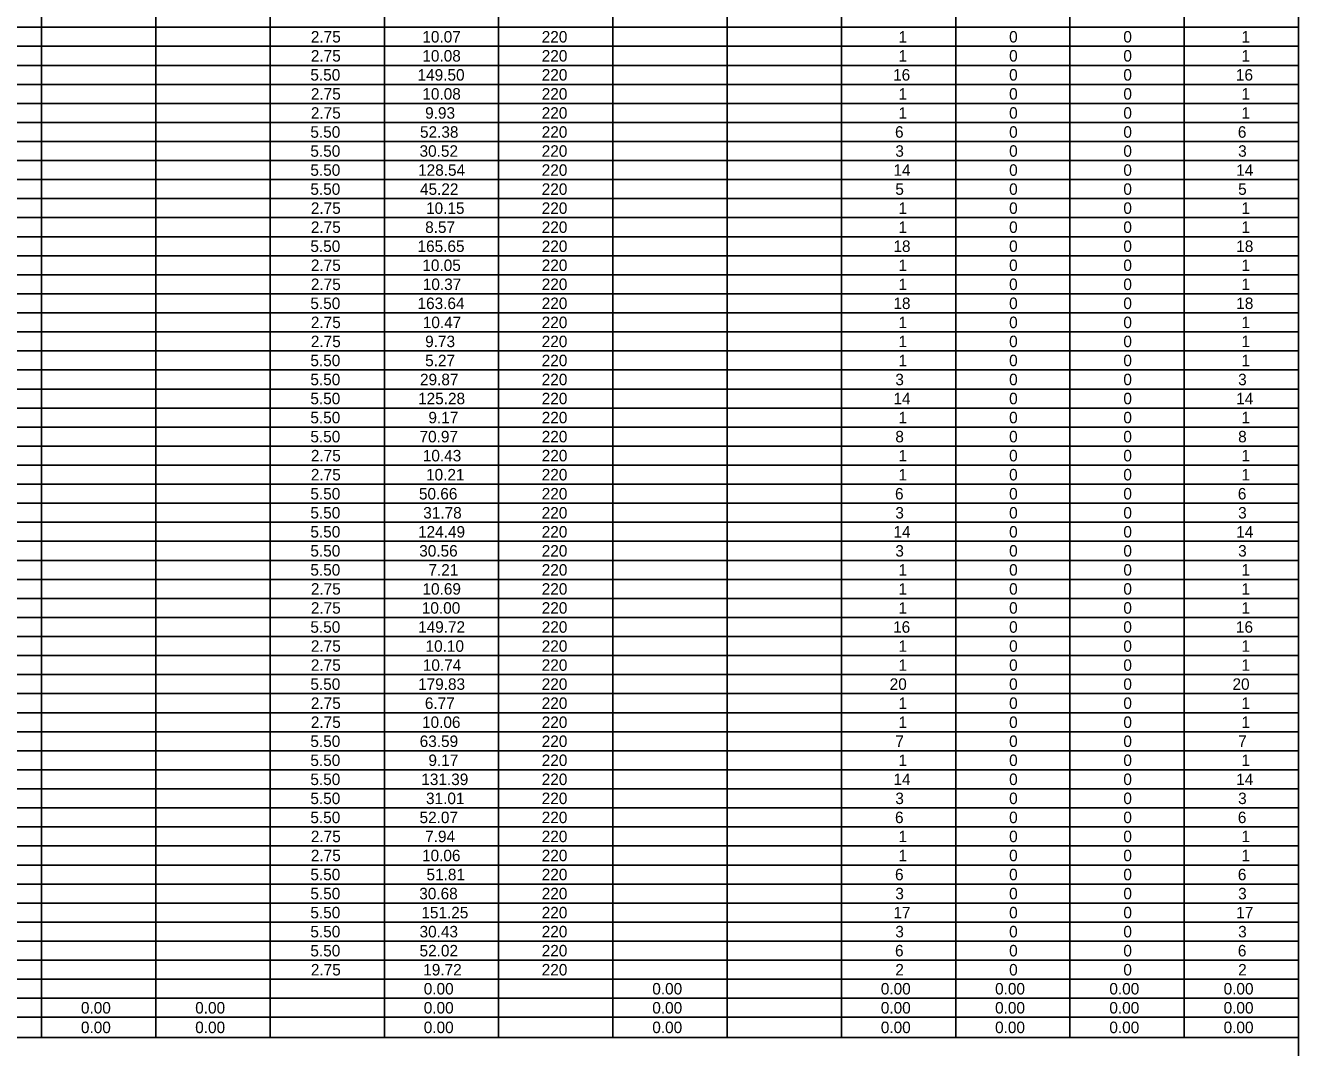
# Model space of a CAD drawing. Extents: x 1226590 to 1228573, y 151304 to 154224.
# Drawn here: x 1228019 to 1228573, y 153319 to 153764 of the extents above; entities that cross this region are included whole.
import ezdxf

# ---------------------------------------------------------------- set-up
doc = ezdxf.new("R2010")
doc.units = 0
doc.layers.add('R_Dimension', color=7, linetype='Continuous')

msp = doc.modelspace()

# ---------------------------------------------------------------- linework, layer by layer
at = {"layer": 'R_Dimension'}
for p, q in [((1228572.93, 152627.62), (1228572.93, 154214.43)), ((1228025.96, 153323.28), (1228025.96, 153928.75)), ((1228075.68, 153323.28), (1228075.68, 153928.75)), ((1228125.41, 153323.28), (1228125.41, 153928.75)), ((1228175.13, 153323.28), (1228175.13, 153928.75)), ((1228224.86, 153323.28), (1228224.86, 153928.75)), ((1228274.58, 153323.28), (1228274.58, 153928.75)), ((1228324.31, 153323.28), (1228324.31, 153928.75)), ((1228374.03, 153323.28), (1228374.03, 153928.75)), ((1228423.76, 153323.28), (1228423.76, 153928.75)), ((1228473.48, 153323.28), (1228473.48, 153928.75)), ((1228523.21, 153323.28), (1228523.21, 153928.75)), ((1226590.27, 153763), (1228572.93, 153763)), ((1226590.27, 153754.72), (1228572.93, 153754.72)), ((1226590.27, 153746.43), (1228572.93, 153746.43)), ((1226590.27, 153738.14), (1228572.93, 153738.14)), ((1226590.27, 153729.85), (1228572.93, 153729.85)), ((1226590.27, 153721.57), (1228572.93, 153721.57)), ((1226590.27, 153713.28), (1228572.93, 153713.28)), ((1226590.27, 153704.99), (1228572.93, 153704.99)), ((1226590.27, 153696.7), (1228572.93, 153696.7)), ((1226590.27, 153688.42), (1228572.93, 153688.42)), ((1226590.27, 153680.13), (1228572.93, 153680.13)), ((1226590.27, 153671.84), (1228572.93, 153671.84)), ((1226590.27, 153663.55), (1228572.93, 153663.55)), ((1226590.27, 153655.27), (1228572.93, 153655.27)), ((1226590.27, 153646.98), (1228572.93, 153646.98)), ((1226590.27, 153638.69), (1228572.93, 153638.69)), ((1226590.27, 153630.4), (1228572.93, 153630.4)), ((1226590.27, 153622.12), (1228572.93, 153622.12)), ((1226590.27, 153613.83), (1228572.93, 153613.83)), ((1226590.27, 153605.54), (1228572.93, 153605.54)), ((1226590.27, 153597.25), (1228572.93, 153597.25)), ((1226590.27, 153588.97), (1228572.93, 153588.97)), ((1226590.27, 153580.68), (1228572.93, 153580.68)), ((1226590.27, 153572.39), (1228572.93, 153572.39)), ((1226590.27, 153564.1), (1228572.93, 153564.1)), ((1226590.27, 153555.82), (1228572.93, 153555.82)), ((1226590.27, 153547.53), (1228572.93, 153547.53)), ((1226590.27, 153539.24), (1228572.93, 153539.24)), ((1226590.27, 153530.95), (1228572.93, 153530.95)), ((1226590.27, 153522.67), (1228572.93, 153522.67)), ((1226590.27, 153514.38), (1228572.93, 153514.38)), ((1226590.27, 153506.09), (1228572.93, 153506.09)), ((1226590.27, 153497.8), (1228572.93, 153497.8)), ((1226590.27, 153489.52), (1228572.93, 153489.52)), ((1226590.27, 153481.23), (1228572.93, 153481.23)), ((1226590.27, 153472.94), (1228572.93, 153472.94)), ((1226590.27, 153464.65), (1228572.93, 153464.65)), ((1226590.27, 153456.37), (1228572.93, 153456.37)), ((1226590.27, 153448.08), (1228572.93, 153448.08)), ((1226590.27, 153439.79), (1228572.93, 153439.79)), ((1226590.27, 153431.5), (1228572.93, 153431.5)), ((1226590.27, 153423.22), (1228572.93, 153423.22)), ((1226590.27, 153414.93), (1228572.93, 153414.93)), ((1226590.27, 153406.64), (1228572.93, 153406.64)), ((1226590.27, 153398.35), (1228572.93, 153398.35)), ((1226590.27, 153390.07), (1228572.93, 153390.07)), ((1226590.27, 153381.78), (1228572.93, 153381.78)), ((1226590.27, 153373.49), (1228572.93, 153373.49)), ((1226590.27, 153365.2), (1228572.93, 153365.2)), ((1226590.27, 153356.92), (1228572.93, 153356.92)), ((1226590.27, 153348.63), (1228572.93, 153348.63)), ((1226590.27, 153340.34), (1228572.93, 153340.34)), ((1226590.27, 153332.05), (1228572.93, 153332.05)), ((1226590.27, 153323.28), (1228572.93, 153323.28))]:
    msp.add_line(p, q, dxfattribs=at)

# ---------------------------------------------------------------- texts
for s, p in [('2.75', (1228143.14, 153756.36)), ('10.07', (1228191.65, 153756.36)), ('220', (1228243.6, 153756.36)), ('1', (1228398.9, 153756.36)), ('0', (1228446.99, 153756.36)), ('0', (1228496.71, 153756.36)), ('1', (1228548.07, 153756.36)), ('2.75', (1228143.14, 153748.07)), ('10.08', (1228191.65, 153748.07)), ('220', (1228243.6, 153748.07)), ('1', (1228398.9, 153748.07)), ('0', (1228446.99, 153748.07)), ('0', (1228496.71, 153748.07)), ('1', (1228548.07, 153748.07)), ('5.50', (1228142.93, 153739.79)), ('149.50', (1228189.58, 153739.79)), ('220', (1228243.6, 153739.79)), ('16', (1228396.51, 153739.79)), ('0', (1228446.99, 153739.79)), ('0', (1228496.71, 153739.79)), ('16', (1228545.69, 153739.79)), ('2.75', (1228143.14, 153731.5)), ('10.08', (1228191.65, 153731.5)), ('220', (1228243.6, 153731.5)), ('1', (1228398.9, 153731.5)), ('0', (1228446.99, 153731.5)), ('0', (1228496.71, 153731.5)), ('1', (1228548.07, 153731.5)), ('2.75', (1228143.14, 153723.21)), ('9.93', (1228192.87, 153723.21)), ('220', (1228243.6, 153723.21)), ('1', (1228398.9, 153723.21)), ('0', (1228446.99, 153723.21)), ('0', (1228496.71, 153723.21)), ('1', (1228548.07, 153723.21)), ('5.50', (1228142.93, 153714.92)), ('52.38', (1228190.63, 153714.92)), ('220', (1228243.6, 153714.92)), ('6', (1228397.34, 153714.92)), ('0', (1228446.99, 153714.92)), ('0', (1228496.71, 153714.92)), ('6', (1228546.52, 153714.92)), ('5.50', (1228142.93, 153706.64)), ('30.52', (1228190.43, 153706.64)), ('220', (1228243.6, 153706.64)), ('3', (1228397.48, 153706.64)), ('0', (1228446.99, 153706.64)), ('0', (1228496.71, 153706.64)), ('3', (1228546.65, 153706.64)), ('5.50', (1228142.93, 153698.35)), ('128.54', (1228189.8, 153698.35)), ('220', (1228243.6, 153698.35)), ('14', (1228396.65, 153698.35)), ('0', (1228446.99, 153698.35)), ('0', (1228496.71, 153698.35)), ('14', (1228545.83, 153698.35)), ('5.50', (1228142.93, 153690.06)), ('45.22', (1228190.63, 153690.06)), ('220', (1228243.6, 153690.06)), ('5', (1228397.48, 153690.06)), ('0', (1228446.99, 153690.06)), ('0', (1228496.71, 153690.06)), ('5', (1228546.65, 153690.06)), ('2.75', (1228143.14, 153681.77)), ('10.15', (1228193.26, 153681.77)), ('220', (1228243.6, 153681.77)), ('1', (1228398.9, 153681.77)), ('0', (1228446.99, 153681.77)), ('0', (1228496.71, 153681.77)), ('1', (1228548.07, 153681.77)), ('2.75', (1228143.14, 153673.49)), ('8.57', (1228192.87, 153673.49)), ('220', (1228243.6, 153673.49)), ('1', (1228398.9, 153673.49)), ('0', (1228446.99, 153673.49)), ('0', (1228496.71, 153673.49)), ('1', (1228548.07, 153673.49)), ('5.50', (1228142.93, 153665.2)), ('165.65', (1228189.56, 153665.2)), ('220', (1228243.6, 153665.2)), ('18', (1228396.65, 153665.2)), ('0', (1228446.99, 153665.2)), ('0', (1228496.71, 153665.2)), ('18', (1228545.83, 153665.2)), ('2.75', (1228143.14, 153656.91)), ('10.05', (1228191.65, 153656.91)), ('220', (1228243.6, 153656.91)), ('1', (1228398.9, 153656.91)), ('0', (1228446.99, 153656.91)), ('0', (1228496.71, 153656.91)), ('1', (1228548.07, 153656.91)), ('2.75', (1228143.14, 153648.62)), ('10.37', (1228191.85, 153648.62)), ('220', (1228243.6, 153648.62)), ('1', (1228398.9, 153648.62)), ('0', (1228446.99, 153648.62)), ('0', (1228496.71, 153648.62)), ('1', (1228548.07, 153648.62)), ('5.50', (1228142.93, 153640.34)), ('163.64', (1228189.56, 153640.34)), ('220', (1228243.6, 153640.34)), ('18', (1228396.65, 153640.34)), ('0', (1228446.99, 153640.34)), ('0', (1228496.71, 153640.34)), ('18', (1228545.83, 153640.34)), ('2.75', (1228143.14, 153632.05)), ('10.47', (1228191.85, 153632.05)), ('220', (1228243.6, 153632.05)), ('1', (1228398.9, 153632.05)), ('0', (1228446.99, 153632.05)), ('0', (1228496.71, 153632.05)), ('1', (1228548.07, 153632.05)), ('2.75', (1228143.14, 153623.76)), ('9.73', (1228192.87, 153623.76)), ('220', (1228243.6, 153623.76)), ('1', (1228398.9, 153623.76)), ('0', (1228446.99, 153623.76)), ('0', (1228496.71, 153623.76)), ('1', (1228548.07, 153623.76)), ('5.50', (1228142.93, 153615.47)), ('5.27', (1228192.87, 153615.47)), ('220', (1228243.6, 153615.47)), ('1', (1228398.9, 153615.47)), ('0', (1228446.99, 153615.47)), ('0', (1228496.71, 153615.47)), ('1', (1228548.07, 153615.47)), ('5.50', (1228142.93, 153607.19)), ('29.87', (1228190.63, 153607.19)), ('220', (1228243.6, 153607.19)), ('3', (1228397.48, 153607.19)), ('0', (1228446.99, 153607.19)), ('0', (1228496.71, 153607.19)), ('3', (1228546.65, 153607.19)), ('5.50', (1228142.93, 153598.9)), ('125.28', (1228189.8, 153598.9)), ('220', (1228243.6, 153598.9)), ('14', (1228396.65, 153598.9)), ('0', (1228446.99, 153598.9)), ('0', (1228496.71, 153598.9)), ('14', (1228545.83, 153598.9)), ('5.50', (1228142.93, 153590.61)), ('9.17', (1228194.29, 153590.61)), ('220', (1228243.6, 153590.61)), ('1', (1228398.9, 153590.61)), ('0', (1228446.99, 153590.61)), ('0', (1228496.71, 153590.61)), ('1', (1228548.07, 153590.61)), ('5.50', (1228142.93, 153582.32)), ('70.97', (1228190.43, 153582.32)), ('220', (1228243.6, 153582.32)), ('8', (1228397.48, 153582.32)), ('0', (1228446.99, 153582.32)), ('0', (1228496.71, 153582.32)), ('8', (1228546.65, 153582.32)), ('2.75', (1228143.14, 153574.04)), ('10.43', (1228191.85, 153574.04)), ('220', (1228243.6, 153574.04)), ('1', (1228398.9, 153574.04)), ('0', (1228446.99, 153574.04)), ('0', (1228496.71, 153574.04)), ('1', (1228548.07, 153574.04)), ('2.75', (1228143.14, 153565.75)), ('10.21', (1228193.26, 153565.75)), ('220', (1228243.6, 153565.75)), ('1', (1228398.9, 153565.75)), ('0', (1228446.99, 153565.75)), ('0', (1228496.71, 153565.75)), ('1', (1228548.07, 153565.75)), ('5.50', (1228142.93, 153557.46)), ('50.66', (1228190.17, 153557.46)), ('220', (1228243.6, 153557.46)), ('6', (1228397.34, 153557.46)), ('0', (1228446.99, 153557.46)), ('0', (1228496.71, 153557.46)), ('6', (1228546.52, 153557.46)), ('5.50', (1228142.93, 153549.17)), ('31.78', (1228192.04, 153549.17)), ('220', (1228243.6, 153549.17)), ('3', (1228397.48, 153549.17)), ('0', (1228446.99, 153549.17)), ('0', (1228496.71, 153549.17)), ('3', (1228546.65, 153549.17)), ('5.50', (1228142.93, 153540.89)), ('124.49', (1228189.78, 153540.89)), ('220', (1228243.6, 153540.89)), ('14', (1228396.65, 153540.89)), ('0', (1228446.99, 153540.89)), ('0', (1228496.71, 153540.89)), ('14', (1228545.83, 153540.89)), ('5.50', (1228142.93, 153532.6)), ('30.56', (1228190.29, 153532.6)), ('220', (1228243.6, 153532.6)), ('3', (1228397.48, 153532.6)), ('0', (1228446.99, 153532.6)), ('0', (1228496.71, 153532.6)), ('3', (1228546.65, 153532.6)), ('5.50', (1228142.93, 153524.31)), ('7.21', (1228194.29, 153524.31)), ('220', (1228243.6, 153524.31)), ('1', (1228398.9, 153524.31)), ('0', (1228446.99, 153524.31)), ('0', (1228496.71, 153524.31)), ('1', (1228548.07, 153524.31)), ('2.75', (1228143.14, 153516.02)), ('10.69', (1228191.71, 153516.02)), ('220', (1228243.6, 153516.02)), ('1', (1228398.9, 153516.02)), ('0', (1228446.99, 153516.02)), ('0', (1228496.71, 153516.02)), ('1', (1228548.07, 153516.02)), ('2.75', (1228143.14, 153507.74)), ('10.00', (1228191.43, 153507.74)), ('220', (1228243.6, 153507.74)), ('1', (1228398.9, 153507.74)), ('0', (1228446.99, 153507.74)), ('0', (1228496.71, 153507.74)), ('1', (1228548.07, 153507.74)), ('5.50', (1228142.93, 153499.45)), ('149.72', (1228189.8, 153499.45)), ('220', (1228243.6, 153499.45)), ('16', (1228396.51, 153499.45)), ('0', (1228446.99, 153499.45)), ('0', (1228496.71, 153499.45)), ('16', (1228545.69, 153499.45)), ('2.75', (1228143.14, 153491.16)), ('10.10', (1228193.05, 153491.16)), ('220', (1228243.6, 153491.16)), ('1', (1228398.9, 153491.16)), ('0', (1228446.99, 153491.16)), ('0', (1228496.71, 153491.16)), ('1', (1228548.07, 153491.16)), ('2.75', (1228143.14, 153482.87)), ('10.74', (1228191.85, 153482.87)), ('220', (1228243.6, 153482.87)), ('1', (1228398.9, 153482.87)), ('0', (1228446.99, 153482.87)), ('0', (1228496.71, 153482.87)), ('1', (1228548.07, 153482.87)), ('5.50', (1228142.93, 153474.59)), ('179.83', (1228189.8, 153474.59)), ('220', (1228243.6, 153474.59)), ('20', (1228395.02, 153474.59)), ('0', (1228446.99, 153474.59)), ('0', (1228496.71, 153474.59)), ('20', (1228544.19, 153474.59)), ('2.75', (1228143.14, 153466.3)), ('6.77', (1228192.75, 153466.3)), ('220', (1228243.6, 153466.3)), ('1', (1228398.9, 153466.3)), ('0', (1228446.99, 153466.3)), ('0', (1228496.71, 153466.3)), ('1', (1228548.07, 153466.3)), ('2.75', (1228143.14, 153458.01)), ('10.06', (1228191.51, 153458.01)), ('220', (1228243.6, 153458.01)), ('1', (1228398.9, 153458.01)), ('0', (1228446.99, 153458.01)), ('0', (1228496.71, 153458.01)), ('1', (1228548.07, 153458.01)), ('5.50', (1228142.93, 153449.72)), ('63.59', (1228190.49, 153449.72)), ('220', (1228243.6, 153449.72)), ('7', (1228397.48, 153449.72)), ('0', (1228446.99, 153449.72)), ('0', (1228496.71, 153449.72)), ('7', (1228546.65, 153449.72)), ('5.50', (1228142.93, 153441.44)), ('9.17', (1228194.29, 153441.44)), ('220', (1228243.6, 153441.44)), ('1', (1228398.9, 153441.44)), ('0', (1228446.99, 153441.44)), ('0', (1228496.71, 153441.44)), ('1', (1228548.07, 153441.44)), ('5.50', (1228142.93, 153433.15)), ('131.39', (1228191.2, 153433.15)), ('220', (1228243.6, 153433.15)), ('14', (1228396.65, 153433.15)), ('0', (1228446.99, 153433.15)), ('0', (1228496.71, 153433.15)), ('14', (1228545.83, 153433.15)), ('5.50', (1228142.93, 153424.86)), ('31.01', (1228193.26, 153424.86)), ('220', (1228243.6, 153424.86)), ('3', (1228397.48, 153424.86)), ('0', (1228446.99, 153424.86)), ('0', (1228496.71, 153424.86)), ('3', (1228546.65, 153424.86)), ('5.50', (1228142.93, 153416.57)), ('52.07', (1228190.43, 153416.57)), ('220', (1228243.6, 153416.57)), ('6', (1228397.34, 153416.57)), ('0', (1228446.99, 153416.57)), ('0', (1228496.71, 153416.57)), ('6', (1228546.52, 153416.57)), ('2.75', (1228143.14, 153408.29)), ('7.94', (1228192.87, 153408.29)), ('220', (1228243.6, 153408.29)), ('1', (1228398.9, 153408.29)), ('0', (1228446.99, 153408.29)), ('0', (1228496.71, 153408.29)), ('1', (1228548.07, 153408.29)), ('2.75', (1228143.14, 153400)), ('10.06', (1228191.51, 153400)), ('220', (1228243.6, 153400)), ('1', (1228398.9, 153400)), ('0', (1228446.99, 153400)), ('0', (1228496.71, 153400)), ('1', (1228548.07, 153400)), ('5.50', (1228142.93, 153391.71)), ('51.81', (1228193.46, 153391.71)), ('220', (1228243.6, 153391.71)), ('6', (1228397.34, 153391.71)), ('0', (1228446.99, 153391.71)), ('0', (1228496.71, 153391.71)), ('6', (1228546.52, 153391.71)), ('5.50', (1228142.93, 153383.42)), ('30.68', (1228190.31, 153383.42)), ('220', (1228243.6, 153383.42)), ('3', (1228397.48, 153383.42)), ('0', (1228446.99, 153383.42)), ('0', (1228496.71, 153383.42)), ('3', (1228546.65, 153383.42)), ('5.50', (1228142.93, 153375.14)), ('151.25', (1228191.22, 153375.14)), ('220', (1228243.6, 153375.14)), ('17', (1228396.65, 153375.14)), ('0', (1228446.99, 153375.14)), ('0', (1228496.71, 153375.14)), ('17', (1228545.83, 153375.14)), ('5.50', (1228142.93, 153366.85)), ('30.43', (1228190.43, 153366.85)), ('220', (1228243.6, 153366.85)), ('3', (1228397.48, 153366.85)), ('0', (1228446.99, 153366.85)), ('0', (1228496.71, 153366.85)), ('3', (1228546.65, 153366.85)), ('5.50', (1228142.93, 153358.56)), ('52.02', (1228190.43, 153358.56)), ('220', (1228243.6, 153358.56)), ('6', (1228397.34, 153358.56)), ('0', (1228446.99, 153358.56)), ('0', (1228496.71, 153358.56)), ('6', (1228546.52, 153358.56)), ('2.75', (1228143.14, 153350.27)), ('19.72', (1228192.04, 153350.27)), ('220', (1228243.6, 153350.27)), ('2', (1228397.48, 153350.27)), ('0', (1228446.99, 153350.27)), ('0', (1228496.71, 153350.27)), ('2', (1228546.65, 153350.27)), ('0.00', (1228192.26, 153341.99)), ('0.00', (1228291.71, 153341.99)), ('0.00', (1228391.16, 153341.99)), ('0.00', (1228440.88, 153341.99)), ('0.00', (1228490.61, 153341.99)), ('0.00', (1228540.33, 153341.99)), ('0.00', (1228043.08, 153333.7)), ('0.00', (1228092.81, 153333.7)), ('0.00', (1228192.26, 153333.7)), ('0.00', (1228291.71, 153333.7)), ('0.00', (1228391.16, 153333.7)), ('0.00', (1228440.88, 153333.7)), ('0.00', (1228490.61, 153333.7)), ('0.00', (1228540.33, 153333.7)), ('0.00', (1228043.08, 153325.17)), ('0.00', (1228092.81, 153325.17)), ('0.00', (1228192.26, 153325.17)), ('0.00', (1228291.71, 153325.17)), ('0.00', (1228391.16, 153325.17)), ('0.00', (1228440.88, 153325.17)), ('0.00', (1228490.61, 153325.17)), ('0.00', (1228540.33, 153325.17))]:
    msp.add_text(s, height=5, dxfattribs=at).set_placement(p)

doc.saveas('drawing.dxf')
